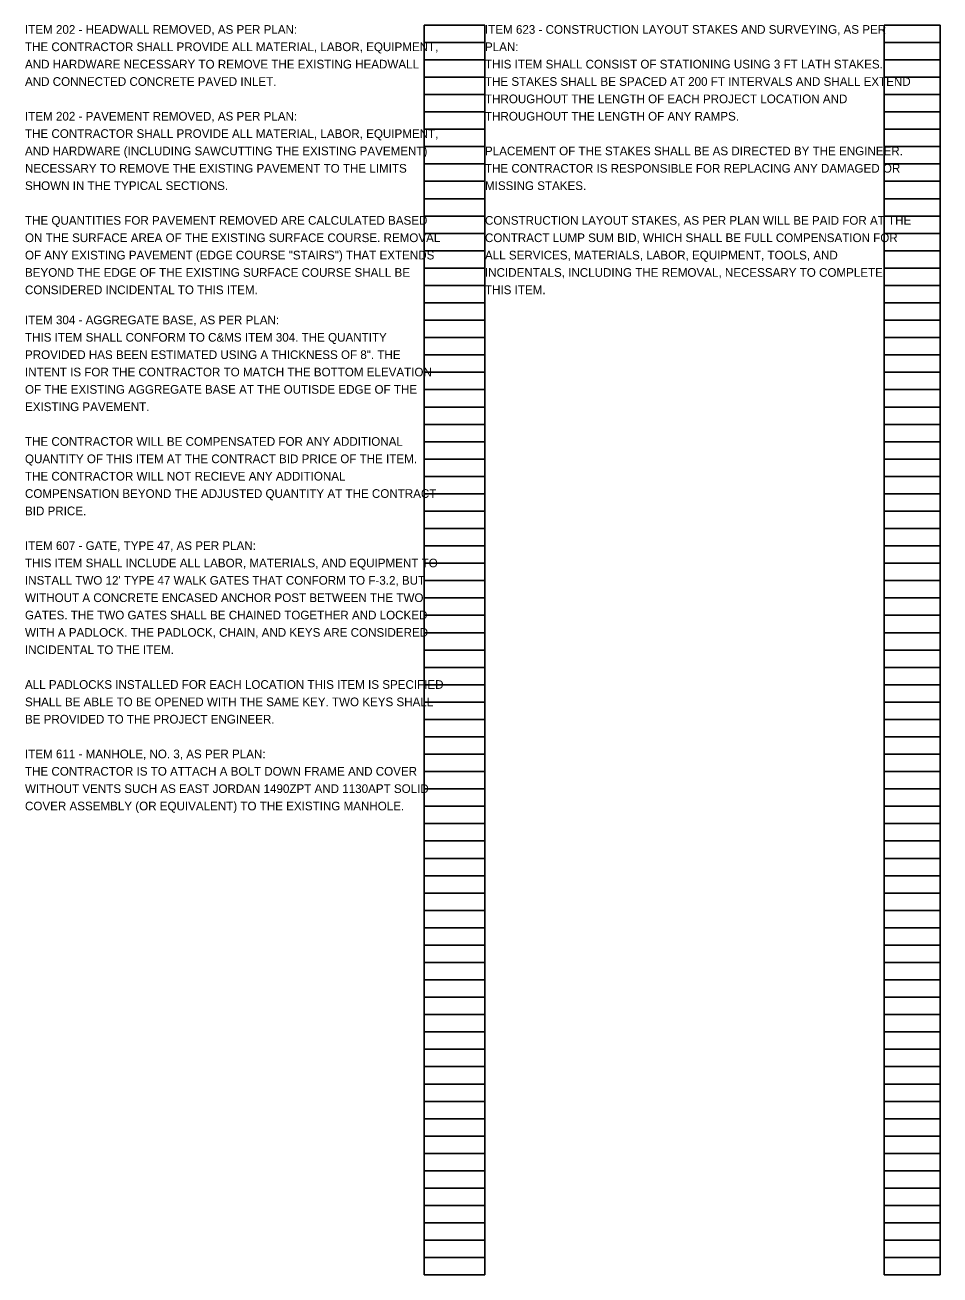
# Model space of a CAD drawing. Extents: x 28758.7 to 28808.5, y 9178.8 to 9230.7.
# Drawn here: x 28793.77 to 28808.53, y 9210.58 to 9230.74 of the extents above; entities that cross this region are included whole.
import ezdxf

# ---------------------------------------------------------------- set-up
doc = ezdxf.new("R2010")
doc.units = 0
doc.layers.add('SH_Data', color=7, linetype='Continuous')
doc.layers.add('SH_Text', color=7, linetype='Continuous')

msp = doc.modelspace()

# ---------------------------------------------------------------- linework, layer by layer
at = {"layer": 'SH_Text'}
for p, q in [((28800.209, 9210.582), (28800.209, 9230.742)), ((28800.209, 9230.742), (28801.189, 9230.742)), ((28801.189, 9210.582), (28801.189, 9230.742)), ((28807.629, 9210.582), (28807.629, 9230.742)), ((28807.629, 9230.742), (28808.529, 9230.742)), ((28808.529, 9210.582), (28808.529, 9230.742)), ((28800.209, 9230.462), (28801.189, 9230.462)), ((28807.629, 9230.462), (28808.529, 9230.462)), ((28800.209, 9230.182), (28801.189, 9230.182)), ((28807.629, 9230.182), (28808.529, 9230.182)), ((28800.209, 9229.902), (28801.189, 9229.902)), ((28807.629, 9229.902), (28808.529, 9229.902)), ((28800.209, 9229.622), (28801.189, 9229.622)), ((28807.629, 9229.622), (28808.529, 9229.622)), ((28800.209, 9229.342), (28801.189, 9229.342)), ((28807.629, 9229.342), (28808.529, 9229.342)), ((28800.209, 9229.062), (28801.189, 9229.062)), ((28807.629, 9229.062), (28808.529, 9229.062)), ((28800.209, 9228.782), (28801.189, 9228.782)), ((28807.629, 9228.782), (28808.529, 9228.782)), ((28800.209, 9228.502), (28801.189, 9228.502)), ((28807.629, 9228.502), (28808.529, 9228.502)), ((28800.209, 9228.222), (28801.189, 9228.222)), ((28807.629, 9228.222), (28808.529, 9228.222)), ((28800.209, 9227.942), (28801.189, 9227.942)), ((28807.629, 9227.942), (28808.529, 9227.942)), ((28800.209, 9227.662), (28801.189, 9227.662)), ((28807.629, 9227.662), (28808.529, 9227.662)), ((28800.209, 9227.382), (28801.189, 9227.382)), ((28807.629, 9227.382), (28808.529, 9227.382)), ((28800.209, 9227.102), (28801.189, 9227.102)), ((28807.629, 9227.102), (28808.529, 9227.102)), ((28800.209, 9226.822), (28801.189, 9226.822)), ((28807.629, 9226.822), (28808.529, 9226.822)), ((28800.209, 9226.542), (28801.189, 9226.542)), ((28807.629, 9226.542), (28808.529, 9226.542)), ((28800.209, 9226.262), (28801.189, 9226.262)), ((28807.629, 9226.262), (28808.529, 9226.262)), ((28800.209, 9225.982), (28801.189, 9225.982)), ((28807.629, 9225.982), (28808.529, 9225.982)), ((28800.209, 9225.702), (28801.189, 9225.702)), ((28807.629, 9225.702), (28808.529, 9225.702)), ((28800.209, 9225.422), (28801.189, 9225.422)), ((28807.629, 9225.422), (28808.529, 9225.422)), ((28800.209, 9225.142), (28801.189, 9225.142)), ((28807.629, 9225.142), (28808.529, 9225.142)), ((28800.209, 9224.862), (28801.189, 9224.862)), ((28807.629, 9224.862), (28808.529, 9224.862)), ((28800.209, 9224.582), (28801.189, 9224.582)), ((28807.629, 9224.582), (28808.529, 9224.582)), ((28800.209, 9224.302), (28801.189, 9224.302)), ((28807.629, 9224.302), (28808.529, 9224.302)), ((28800.209, 9224.022), (28801.189, 9224.022)), ((28807.629, 9224.022), (28808.529, 9224.022)), ((28800.209, 9223.742), (28801.189, 9223.742)), ((28807.629, 9223.742), (28808.529, 9223.742)), ((28800.209, 9223.462), (28801.189, 9223.462)), ((28807.629, 9223.462), (28808.529, 9223.462)), ((28800.209, 9223.182), (28801.189, 9223.182)), ((28807.629, 9223.182), (28808.529, 9223.182)), ((28800.209, 9222.902), (28801.189, 9222.902)), ((28807.629, 9222.902), (28808.529, 9222.902)), ((28800.209, 9222.622), (28801.189, 9222.622)), ((28807.629, 9222.622), (28808.529, 9222.622)), ((28800.209, 9222.342), (28801.189, 9222.342)), ((28807.629, 9222.342), (28808.529, 9222.342)), ((28800.209, 9222.062), (28801.189, 9222.062)), ((28807.629, 9222.062), (28808.529, 9222.062)), ((28800.209, 9221.782), (28801.189, 9221.782)), ((28807.629, 9221.782), (28808.529, 9221.782)), ((28800.209, 9221.502), (28801.189, 9221.502)), ((28807.629, 9221.502), (28808.529, 9221.502)), ((28800.209, 9221.222), (28801.189, 9221.222)), ((28807.629, 9221.222), (28808.529, 9221.222)), ((28800.209, 9220.942), (28801.189, 9220.942)), ((28807.629, 9220.942), (28808.529, 9220.942)), ((28800.209, 9220.662), (28801.189, 9220.662)), ((28807.629, 9220.662), (28808.529, 9220.662)), ((28800.209, 9220.382), (28801.189, 9220.382)), ((28807.629, 9220.382), (28808.529, 9220.382)), ((28800.209, 9220.102), (28801.189, 9220.102)), ((28807.629, 9220.102), (28808.529, 9220.102)), ((28800.209, 9219.822), (28801.189, 9219.822)), ((28807.629, 9219.822), (28808.529, 9219.822)), ((28800.209, 9219.542), (28801.189, 9219.542)), ((28807.629, 9219.542), (28808.529, 9219.542)), ((28800.209, 9219.262), (28801.189, 9219.262)), ((28807.629, 9219.262), (28808.529, 9219.262)), ((28800.209, 9218.982), (28801.189, 9218.982)), ((28807.629, 9218.982), (28808.529, 9218.982)), ((28800.209, 9218.702), (28801.189, 9218.702)), ((28807.629, 9218.702), (28808.529, 9218.702)), ((28800.209, 9218.422), (28801.189, 9218.422)), ((28807.629, 9218.422), (28808.529, 9218.422)), ((28800.209, 9218.142), (28801.189, 9218.142)), ((28807.629, 9218.142), (28808.529, 9218.142)), ((28800.209, 9217.862), (28801.189, 9217.862)), ((28807.629, 9217.862), (28808.529, 9217.862)), ((28800.209, 9217.582), (28801.189, 9217.582)), ((28807.629, 9217.582), (28808.529, 9217.582)), ((28800.209, 9217.302), (28801.189, 9217.302)), ((28807.629, 9217.302), (28808.529, 9217.302)), ((28800.209, 9217.022), (28801.189, 9217.022)), ((28807.629, 9217.022), (28808.529, 9217.022)), ((28800.209, 9216.742), (28801.189, 9216.742)), ((28807.629, 9216.742), (28808.529, 9216.742)), ((28800.209, 9216.462), (28801.189, 9216.462)), ((28807.629, 9216.462), (28808.529, 9216.462)), ((28800.209, 9216.182), (28801.189, 9216.182)), ((28807.629, 9216.182), (28808.529, 9216.182)), ((28800.209, 9215.902), (28801.189, 9215.902)), ((28807.629, 9215.902), (28808.529, 9215.902)), ((28800.209, 9215.622), (28801.189, 9215.622)), ((28807.629, 9215.622), (28808.529, 9215.622)), ((28800.209, 9215.342), (28801.189, 9215.342)), ((28807.629, 9215.342), (28808.529, 9215.342)), ((28800.209, 9215.062), (28801.189, 9215.062)), ((28807.629, 9215.062), (28808.529, 9215.062)), ((28800.209, 9214.782), (28801.189, 9214.782)), ((28807.629, 9214.782), (28808.529, 9214.782)), ((28800.209, 9214.502), (28801.189, 9214.502)), ((28807.629, 9214.502), (28808.529, 9214.502)), ((28800.209, 9214.222), (28801.189, 9214.222)), ((28807.629, 9214.222), (28808.529, 9214.222)), ((28800.209, 9213.942), (28801.189, 9213.942)), ((28807.629, 9213.942), (28808.529, 9213.942)), ((28800.209, 9213.662), (28801.189, 9213.662)), ((28807.629, 9213.662), (28808.529, 9213.662)), ((28800.209, 9213.382), (28801.189, 9213.382)), ((28807.629, 9213.382), (28808.529, 9213.382)), ((28800.209, 9213.102), (28801.189, 9213.102)), ((28807.629, 9213.102), (28808.529, 9213.102)), ((28800.209, 9212.822), (28801.189, 9212.822)), ((28807.629, 9212.822), (28808.529, 9212.822)), ((28800.209, 9212.542), (28801.189, 9212.542)), ((28807.629, 9212.542), (28808.529, 9212.542)), ((28800.209, 9212.262), (28801.189, 9212.262)), ((28807.629, 9212.262), (28808.529, 9212.262)), ((28800.209, 9211.982), (28801.189, 9211.982)), ((28807.629, 9211.982), (28808.529, 9211.982)), ((28800.209, 9211.702), (28801.189, 9211.702)), ((28807.629, 9211.702), (28808.529, 9211.702)), ((28800.209, 9211.422), (28801.189, 9211.422)), ((28807.629, 9211.422), (28808.529, 9211.422)), ((28800.209, 9211.142), (28801.189, 9211.142)), ((28807.629, 9211.142), (28808.529, 9211.142)), ((28800.209, 9210.862), (28801.189, 9210.862)), ((28807.629, 9210.862), (28808.529, 9210.862)), ((28800.209, 9210.582), (28801.189, 9210.582)), ((28807.629, 9210.582), (28808.529, 9210.582))]:
    msp.add_line(p, q, dxfattribs=at)

# ---------------------------------------------------------------- texts
at = {"layer": 'SH_Data'}
for s, p in [('ITEM 202 - HEADWALL REMOVED, AS PER PLAN:', (28793.769, 9230.602)), ('ITEM 623 - CONSTRUCTION LAYOUT STAKES AND SURVEYING, AS PER ', (28801.189, 9230.602)), ('THE CONTRACTOR SHALL PROVIDE ALL MATERIAL, LABOR, EQUIPMENT, ', (28793.769, 9230.322)), ('PLAN:', (28801.189, 9230.322)), ('AND HARDWARE NECESSARY TO REMOVE THE EXISTING HEADWALL ', (28793.769, 9230.042)), ('THIS ITEM SHALL CONSIST OF STATIONING USING 3 FT LATH STAKES. ', (28801.189, 9230.042)), ('AND CONNECTED CONCRETE PAVED INLET.', (28793.769, 9229.762)), ('THE STAKES SHALL BE SPACED AT 200 FT INTERVALS AND SHALL EXTEND ', (28801.189, 9229.762)), ('THROUGHOUT THE LENGTH OF EACH PROJECT LOCATION AND ', (28801.189, 9229.482)), ('ITEM 202 - PAVEMENT REMOVED, AS PER PLAN:', (28793.769, 9229.202)), ('THROUGHOUT THE LENGTH OF ANY RAMPS. ', (28801.189, 9229.202)), ('THE CONTRACTOR SHALL PROVIDE ALL MATERIAL, LABOR, EQUIPMENT, ', (28793.769, 9228.922)), ('AND HARDWARE (INCLUDING SAWCUTTING THE EXISTING PAVEMENT) ', (28793.769, 9228.642)), ('PLACEMENT OF THE STAKES SHALL BE AS DIRECTED BY THE ENGINEER. ', (28801.189, 9228.642)), ('NECESSARY TO REMOVE THE EXISTING PAVEMENT TO THE LIMITS ', (28793.769, 9228.362)), ('THE CONTRACTOR IS RESPONSIBLE FOR REPLACING ANY DAMAGED OR ', (28801.189, 9228.362)), ('SHOWN IN THE TYPICAL SECTIONS.', (28793.769, 9228.082)), ('MISSING STAKES.', (28801.189, 9228.082)), ('THE QUANTITIES FOR PAVEMENT REMOVED ARE CALCULATED BASED ', (28793.769, 9227.522)), ('CONSTRUCTION LAYOUT STAKES, AS PER PLAN WILL BE PAID FOR AT THE ', (28801.189, 9227.522)), ('ON THE SURFACE AREA OF THE EXISTING SURFACE COURSE. REMOVAL ', (28793.769, 9227.242)), ('CONTRACT LUMP SUM BID, WHICH SHALL BE FULL COMPENSATION FOR ', (28801.189, 9227.242)), ('OF ANY EXISTING PAVEMENT (EDGE COURSE "STAIRS") THAT EXTENDS ', (28793.769, 9226.962)), ('ALL SERVICES, MATERIALS, LABOR, EQUIPMENT, TOOLS, AND ', (28801.189, 9226.962)), ('BEYOND THE EDGE OF THE EXISTING SURFACE COURSE SHALL BE ', (28793.769, 9226.682)), ('INCIDENTALS, INCLUDING THE REMOVAL, NECESSARY TO COMPLETE ', (28801.189, 9226.682)), ('CONSIDERED INCIDENTAL TO THIS ITEM.', (28793.769, 9226.402)), ('THIS ITEM.', (28801.189, 9226.402)), ('ITEM 304 - AGGREGATE BASE, AS PER PLAN:', (28793.769, 9225.916)), ('THIS ITEM SHALL CONFORM TO C&MS ITEM 304. THE QUANTITY ', (28793.769, 9225.636)), ('PROVIDED HAS BEEN ESTIMATED USING A THICKNESS OF 8". THE ', (28793.769, 9225.356)), ('INTENT IS FOR THE CONTRACTOR TO MATCH THE BOTTOM ELEVATION ', (28793.769, 9225.076)), ('OF THE EXISTING AGGREGATE BASE AT THE OUTISDE EDGE OF THE ', (28793.769, 9224.796)), ('EXISTING PAVEMENT.', (28793.769, 9224.516)), ('THE CONTRACTOR WILL BE COMPENSATED FOR ANY ADDITIONAL ', (28793.769, 9223.956)), ('QUANTITY OF THIS ITEM AT THE CONTRACT BID PRICE OF THE ITEM. ', (28793.769, 9223.676)), ('THE CONTRACTOR WILL NOT RECIEVE ANY ADDITIONAL ', (28793.769, 9223.396)), ('COMPENSATION BEYOND THE ADJUSTED QUANTITY AT THE CONTRACT ', (28793.769, 9223.116)), ('BID PRICE.', (28793.769, 9222.836)), ('ITEM 607 - GATE, TYPE 47, AS PER PLAN:', (28793.769, 9222.276)), ('THIS ITEM SHALL INCLUDE ALL LABOR, MATERIALS, AND EQUIPMENT TO ', (28793.769, 9221.996)), ("INSTALL TWO 12' TYPE 47 WALK GATES THAT CONFORM TO F-3.2, BUT ", (28793.769, 9221.716)), ('WITHOUT A CONCRETE ENCASED ANCHOR POST BETWEEN THE TWO ', (28793.769, 9221.436)), ('GATES. THE TWO GATES SHALL BE CHAINED TOGETHER AND LOCKED ', (28793.769, 9221.156)), ('WITH A PADLOCK. THE PADLOCK, CHAIN, AND KEYS ARE CONSIDERED ', (28793.769, 9220.876)), ('INCIDENTAL TO THE ITEM. ', (28793.769, 9220.596)), ('ALL PADLOCKS INSTALLED FOR EACH LOCATION THIS ITEM IS SPECIFIED ', (28793.769, 9220.036)), ('SHALL BE ABLE TO BE OPENED WITH THE SAME KEY. TWO KEYS SHALL ', (28793.769, 9219.756)), ('BE PROVIDED TO THE PROJECT ENGINEER.', (28793.769, 9219.476)), ('ITEM 611 - MANHOLE, NO. 3, AS PER PLAN:', (28793.769, 9218.916)), ('THE CONTRACTOR IS TO ATTACH A BOLT DOWN FRAME AND COVER ', (28793.769, 9218.636)), ('WITHOUT VENTS SUCH AS EAST JORDAN 1490ZPT AND 1130APT SOLID ', (28793.769, 9218.356)), ('COVER ASSEMBLY (OR EQUIVALENT) TO THE EXISTING MANHOLE. ', (28793.769, 9218.076))]:
    msp.add_text(s, height=0.14, dxfattribs=at).set_placement(p)

doc.saveas('drawing.dxf')
